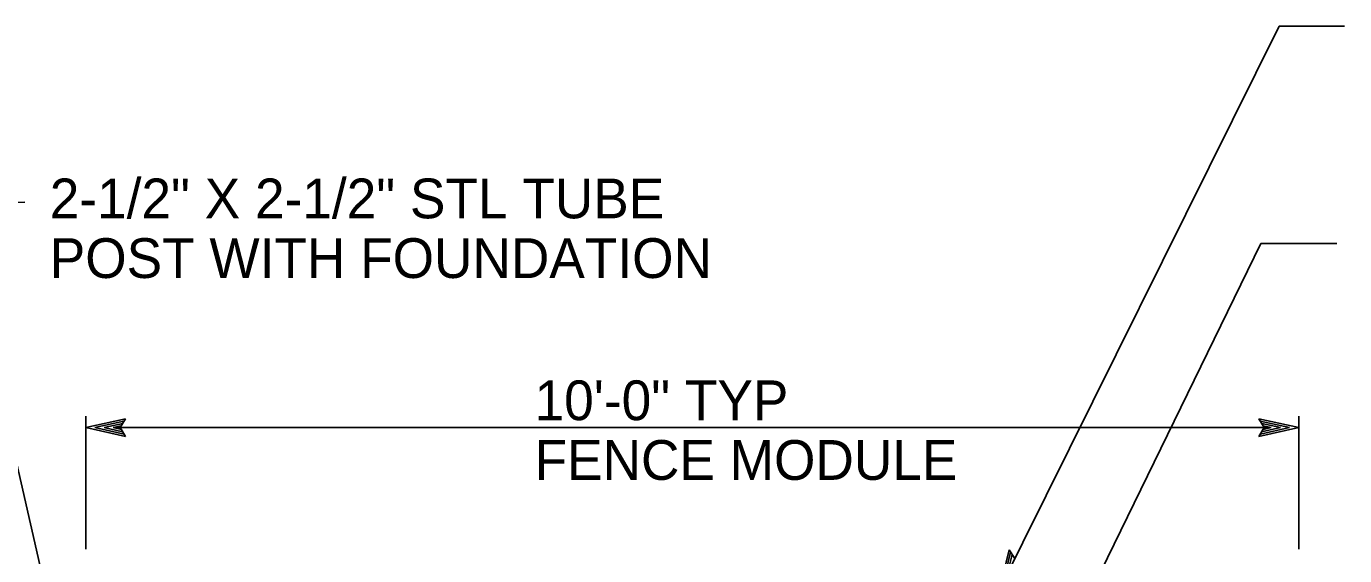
# Model space of a CAD drawing. Extents: x 6710407 to 6714861, y 1868090 to 1871317.
# Drawn here: x 6711630.5 to 6711829.3, y 1869898.7 to 1869978.5 of the extents above; entities that cross this region are included whole.
import ezdxf

# ---------------------------------------------------------------- set-up
doc = ezdxf.new("R2010")
doc.units = 0
for name, color, linetype in [('G-MARK', 7, 'Continuous'), ('G-TEXT', 7, 'Continuous'), ('Nongeo Data(60)', 7, 'Continuous')]:
    doc.layers.add(name, color=color, linetype=linetype)

msp = doc.modelspace()

# ---------------------------------------------------------------- linework, layer by layer
at = {"layer": 'G-MARK'}
for p, q in [((6711819.43, 1869978.52), (6711829.31, 1869978.52)), ((6711816.65, 1869945.77), (6711828.15, 1869945.77)), ((6711639.5, 1869899.67), (6711639.5, 1869919.71)), ((6711822.38, 1869899.67), (6711822.38, 1869919.71)), ((6711644.07, 1869917.99), (6711817.81, 1869917.99))]:
    msp.add_line(p, q, dxfattribs=at)
for points in [[(6711777.25, 1869893.59), (6711819.43, 1869978.52), (6711819.43, 1869978.52)], [(6711637.97, 1869873.68), (6711620.12, 1869951.83), (6711630.31, 1869951.98)], [(6711788.55, 1869888.05), (6711816.65, 1869945.77), (6711816.65, 1869945.77)]]:
    msp.add_lwpolyline(points, dxfattribs=at)
at = {"layer": 'G-TEXT'}
for p, q in [((6711639.5, 1869917.99), (6711645.5, 1869919.32)), ((6711640.89, 1869918), (6711645.26, 1869918.96)), ((6711642.26, 1869917.99), (6711645.09, 1869918.62)), ((6711643.64, 1869917.99), (6711644.85, 1869918.26)), ((6711645.5, 1869919.32), (6711644.7, 1869917.99)), ((6711645.5, 1869919.32), (6711645.5, 1869919.32)), ((6711817.18, 1869917.99), (6711816.38, 1869919.33)), ((6711816.38, 1869919.33), (6711816.38, 1869919.33)), ((6711816.38, 1869919.33), (6711822.38, 1869917.99)), ((6711816.59, 1869918.98), (6711821, 1869917.99)), ((6711816.83, 1869918.62), (6711819.62, 1869917.99)), ((6711817, 1869918.27), (6711818.23, 1869918)), ((6711645.5, 1869916.65), (6711639.5, 1869917.99)), ((6711639.5, 1869917.99), (6711639.5, 1869917.99)), ((6711645.28, 1869917.01), (6711640.88, 1869917.99)), ((6711645.05, 1869917.37), (6711642.26, 1869917.99)), ((6711644.87, 1869917.71), (6711643.64, 1869917.99)), ((6711644.7, 1869917.99), (6711645.5, 1869916.65)), ((6711645.5, 1869916.65), (6711645.5, 1869916.65)), ((6711822.38, 1869917.99), (6711816.38, 1869916.66)), ((6711816.38, 1869916.66), (6711817.18, 1869917.99)), ((6711816.38, 1869916.66), (6711816.38, 1869916.66)), ((6711820.99, 1869917.99), (6711816.61, 1869917.02)), ((6711819.62, 1869917.99), (6711816.79, 1869917.37)), ((6711818.23, 1869918), (6711817.03, 1869917.73)), ((6711822.38, 1869917.99), (6711822.38, 1869917.99)), ((6711777.25, 1869893.59), (6711778.73, 1869899.55)), ((6711777.86, 1869894.84), (6711778.95, 1869899.18)), ((6711778.48, 1869896.06), (6711779.18, 1869898.87)), ((6711778.73, 1869899.55), (6711778.73, 1869899.55)), ((6711778.73, 1869899.55), (6711779.57, 1869898.24))]:
    msp.add_line(p, q, dxfattribs=at)
at = {"layer": 'Nongeo Data(60)'}
msp.add_line((6711822.38, 1869917.99), (6711822.38, 1869917.99), dxfattribs=at)

# ---------------------------------------------------------------- texts
for s, p in [('2-1/2" X 2-1/2" STL TUBE', (6711634.07, 1869949.56)), ('POST WITH FOUNDATION', (6711634.07, 1869940.56)), ('10\'-0" TYP', (6711707.17, 1869919.11)), ('FENCE MODULE', (6711707.17, 1869910.11))]:
    msp.add_text(s, height=6, dxfattribs=at).set_placement(p)

doc.saveas('drawing.dxf')
